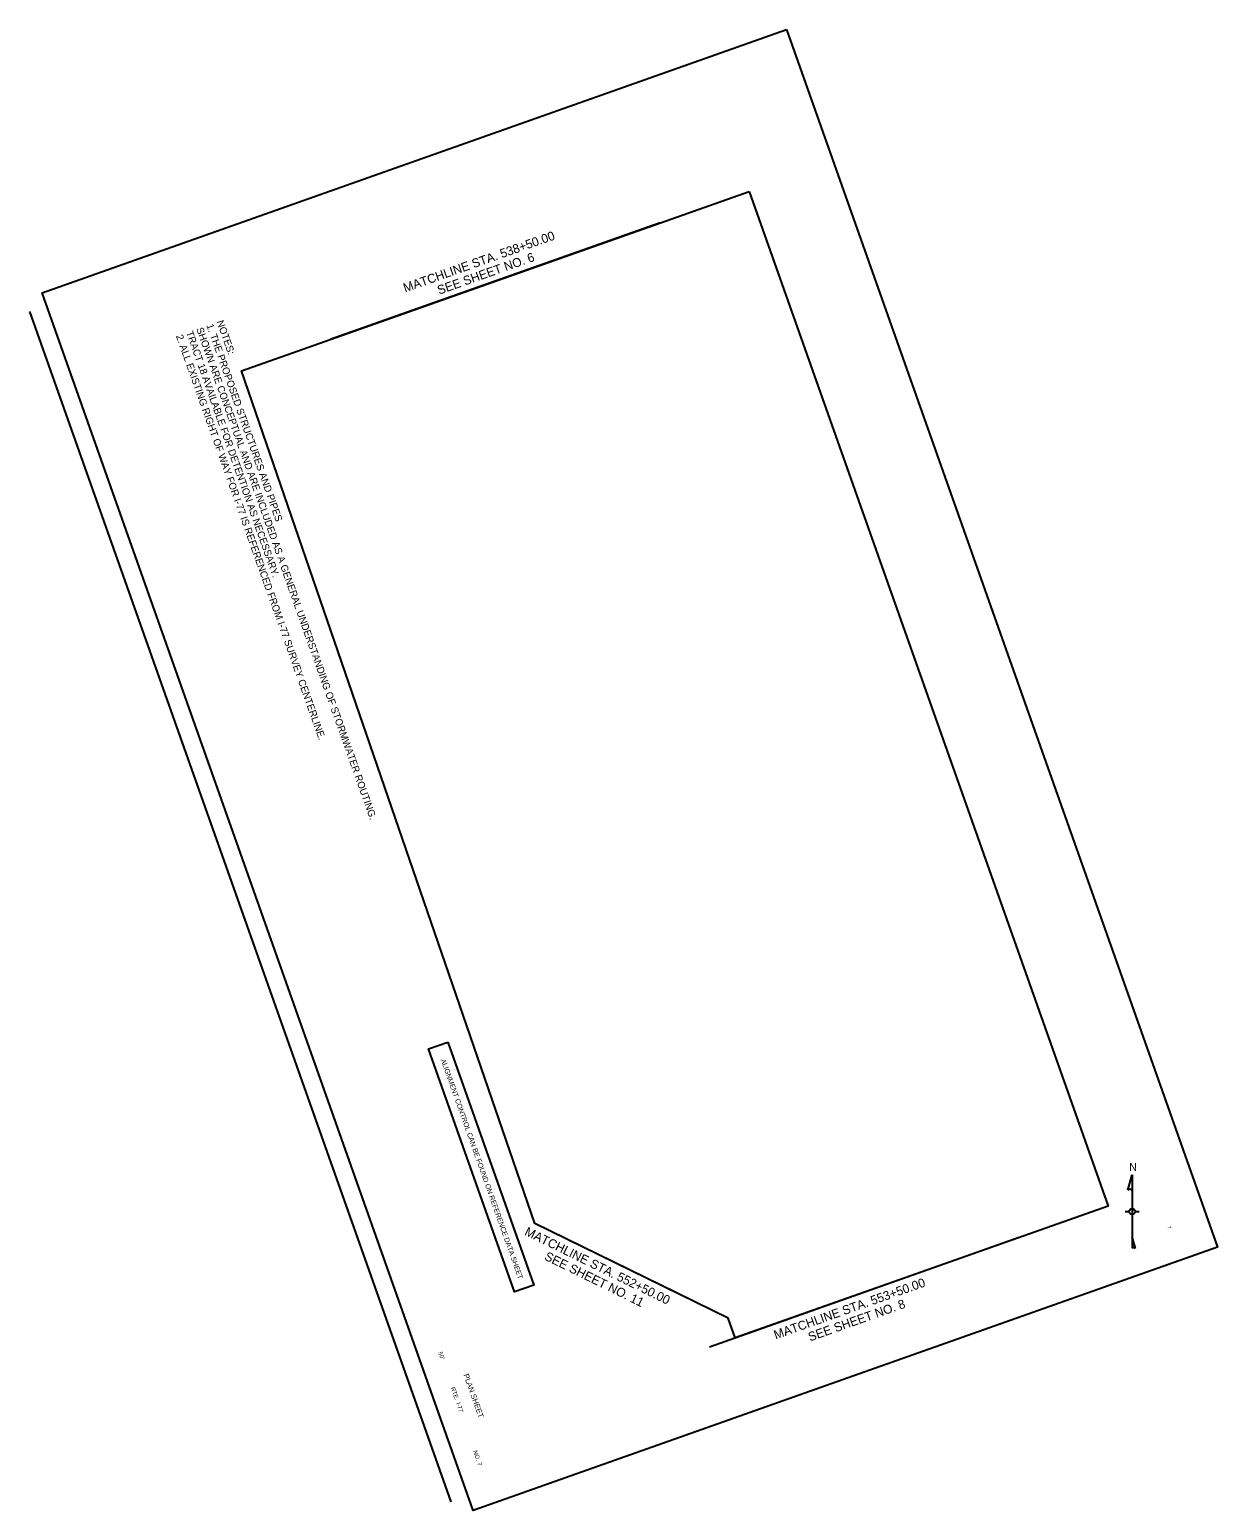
# Model space of a CAD drawing. Extents: x 2004548 to 2006202, y 1137485 to 1139549.
import ezdxf

# ---------------------------------------------------------------- set-up
doc = ezdxf.new("R2010")
doc.units = 0
for name, color, linetype in [('North Arrow', 7, 'Continuous'), ('RD_SHT_IplotShp', 7, 'Continuous'), ('RD_SHT_MatchLine', 7, 'Continuous'), ('RD_SHT_Misc1', 7, 'Continuous'), ('RD_SHT_ShtClip', 7, 'Continuous'), ('RD_SHT_TX', 7, 'Continuous')]:
    doc.layers.add(name, color=color, linetype=linetype)

msp = doc.modelspace()

# ---------------------------------------------------------------- linework, layer by layer
at = {"layer": 'North Arrow'}
for p, q in [((2006077.7, 1137931.5), (2006083.6, 1137952.5)), ((2006083.6, 1137952.5), (2006083.6, 1137930.4)), ((2006083.6, 1137952.5), (2006083.6, 1137850.3)), ((2006073.9, 1137901.4), (2006079.6, 1137901.4)), ((2006087.6, 1137901.4), (2006093.3, 1137901.4)), ((2006083.6, 1137866.1), (2006083.6, 1137850.3)), ((2006088.1, 1137850.1), (2006083.6, 1137866.1))]:
    msp.add_line(p, q, dxfattribs=at)
msp.add_circle((2006083.6, 1137901.4), 4.02, dxfattribs=at)
for centre, radius, start, end in [((2006080.3, 1137929), 3.59, 22.3707, 136.1387), ((2006085.7, 1137847.8), 3.3, 43.3397, 130.5607)]:
    msp.add_arc(centre, radius, start, end, dxfattribs=at)
at = {"layer": 'RD_SHT_IplotShp'}
msp.add_lwpolyline([(2005602, 1139548.8), (2006202.3, 1137851.9), (2005165.3, 1137485), (2004565, 1139181.9)], close=True, dxfattribs=at)
at = {"layer": 'RD_SHT_MatchLine'}
for p, q in [((2005426.1, 1139279.5), (2004966.5, 1139116.9)), ((2005470.7, 1137777.3), (2005251.5, 1137884.9)), ((2005926.3, 1137865.4), (2005494.7, 1137712.7))]:
    msp.add_line(p, q, dxfattribs=at)
at = {"layer": 'RD_SHT_ShtClip'}
msp.add_lwpolyline([(2005549.8, 1139323.3), (2006050.1, 1137909.2), (2005530.3, 1137725.3), (2005520.6, 1137752.8), (2005251.5, 1137884.9), (2004842.7, 1139073.1)], close=True, dxfattribs=at)
at = {"layer": 'RD_SHT_TX'}
msp.add_line((2004547.6, 1139156.1), (2005134.6, 1137496.8), dxfattribs=at)
msp.add_line((2004547.6, 1139156.1), (2005134.6, 1137496.8), dxfattribs=at)
msp.add_lwpolyline([(2005130.3, 1138137.6), (2005250, 1137799), (2005223.3, 1137789.5), (2005103.5, 1138128.1)], close=True, dxfattribs=at)

# ---------------------------------------------------------------- texts
at = {"layer": 'North Arrow'}
msp.add_text('N', height=11.1, dxfattribs=at).set_placement((2006079.5, 1137958))
at = {"layer": 'RD_SHT_MatchLine'}
for s, rotation, p in [('MATCHLINE STA. 538+50.00', 19.482, (2005070.7, 1139182.4)), ('SEE SHEET NO. 6', 19.482, (2005118.2, 1139179.3)), ('MATCHLINE STA. 552+50.00', 333.8563, (2005236.1, 1137869.4)), ('SEE SHEET NO. 11', 333.8563, (2005263.7, 1137834.9)), ('MATCHLINE STA. 553+50.00', 19.482, (2005586.9, 1137723.3)), ('SEE SHEET NO. 8', 19.482, (2005634.8, 1137720.4))]:
    msp.add_text(s, height=12.5, rotation=rotation, dxfattribs=at).set_placement(p)
at = {"layer": 'RD_SHT_Misc1'}
for s, p in [('1. THE PROPOSED STRUCTURES AND PIPES ', (2004793.7, 1139136.7)), ('NOTES:', (2004807.9, 1139141.7)), ('2. ALL EXISTING RIGHT OF WAY FOR I-77 IS REFERENCED FROM I-77 SURVEY CENTERLINE.', (2004751.3, 1139121.7)), ('TRACT 18 AVAILABLE FOR DETENTION AS NECESSARY. ', (2004765.4, 1139126.7)), ('SHOWN ARE CONCEPTUAL AND ARE INCLUDED AS A GENERAL UNDERSTANDING OF STORMWATER ROUTING.  ', (2004779.6, 1139131.7))]:
    msp.add_text(s, height=10, rotation=289.482, dxfattribs=at).set_placement(p)
at = {"layer": 'RD_SHT_TX'}
for s, height, p in [('ALIGNMENT CONTROL CAN BE FOUND ON REFERENCE DATA SHEET', 7, (2005120.2, 1138113)), ('7', 4.5, (2006132.8, 1137880.3)), ("50'", 6, (2005116.7, 1137704.9)), ('PLAN SHEET', 7.5, (2005151.9, 1137673.9)), ('RTE.', 6, (2005134, 1137655.8)), ('I-77', 6, (2005141.6, 1137634.3)), ('NO.', 6, (2005165.3, 1137567.4)), ('7', 6, (2005171.1, 1137551))]:
    msp.add_text(s, height=height, rotation=289.482, dxfattribs=at).set_placement(p)

doc.saveas('drawing.dxf')
